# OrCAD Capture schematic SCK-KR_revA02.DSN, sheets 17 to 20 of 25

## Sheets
17 17_DisplayPort: size Custom
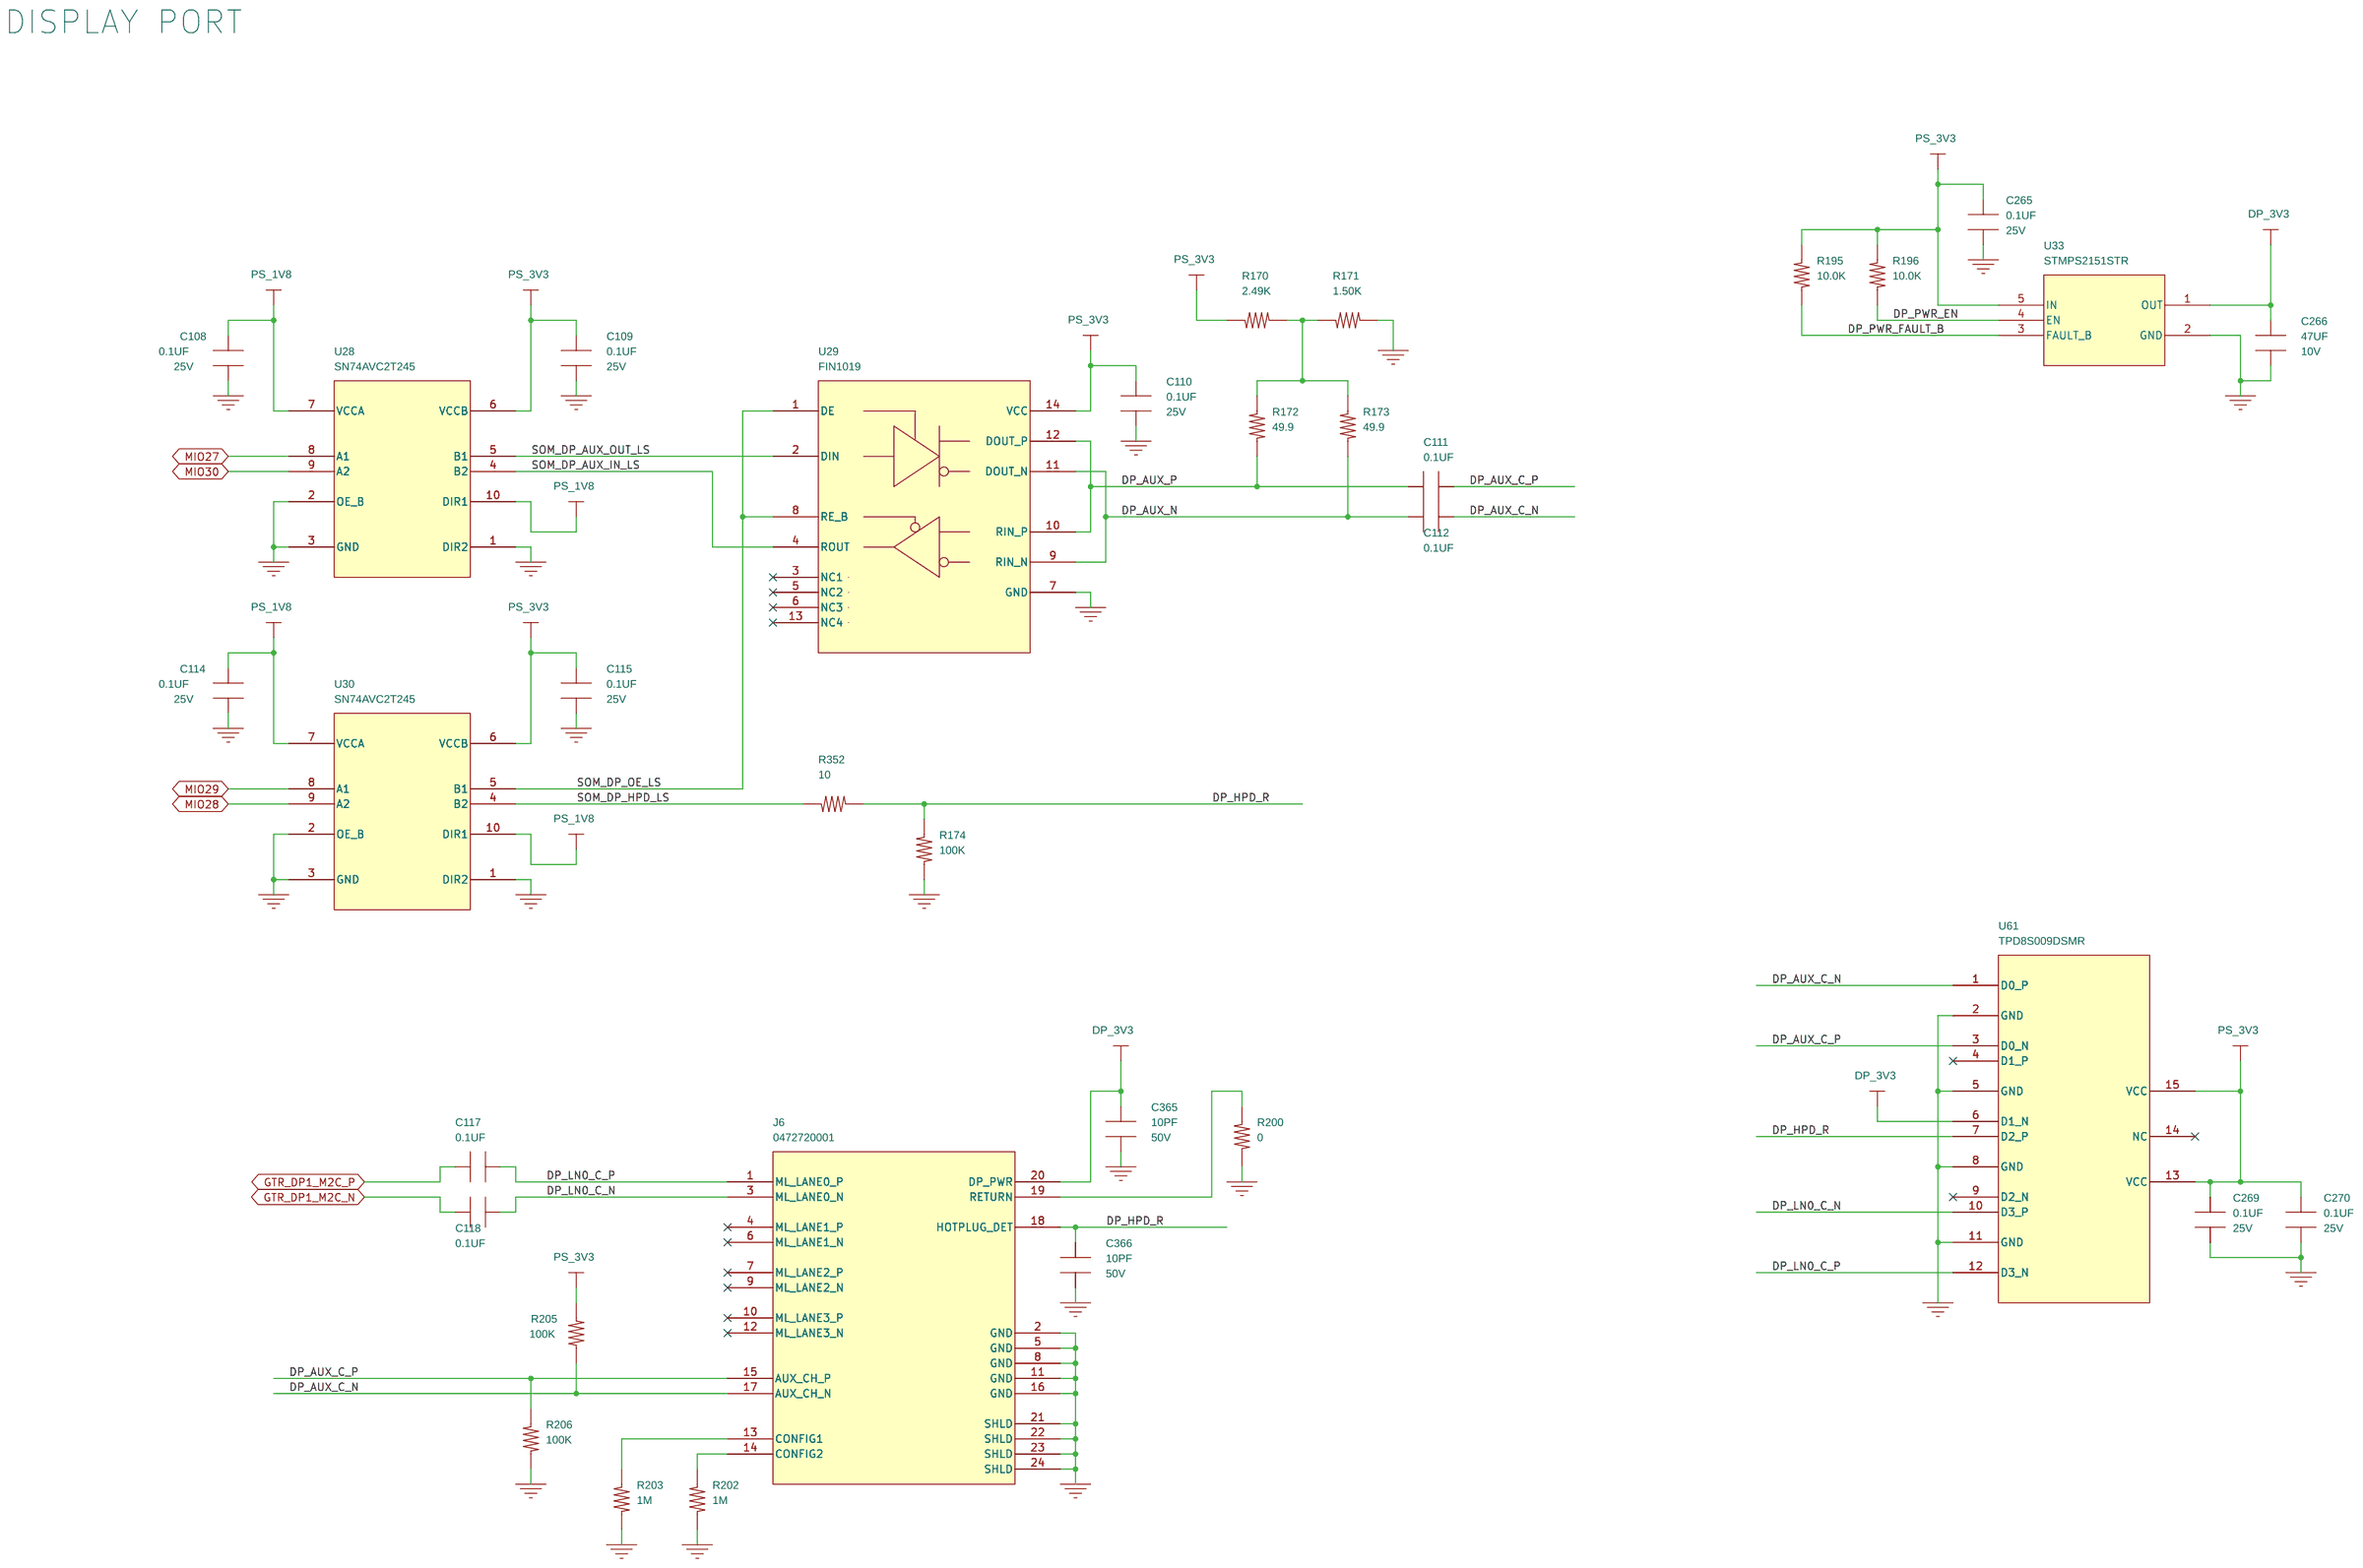
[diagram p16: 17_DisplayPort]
18 18_PS_GEM0: size Custom
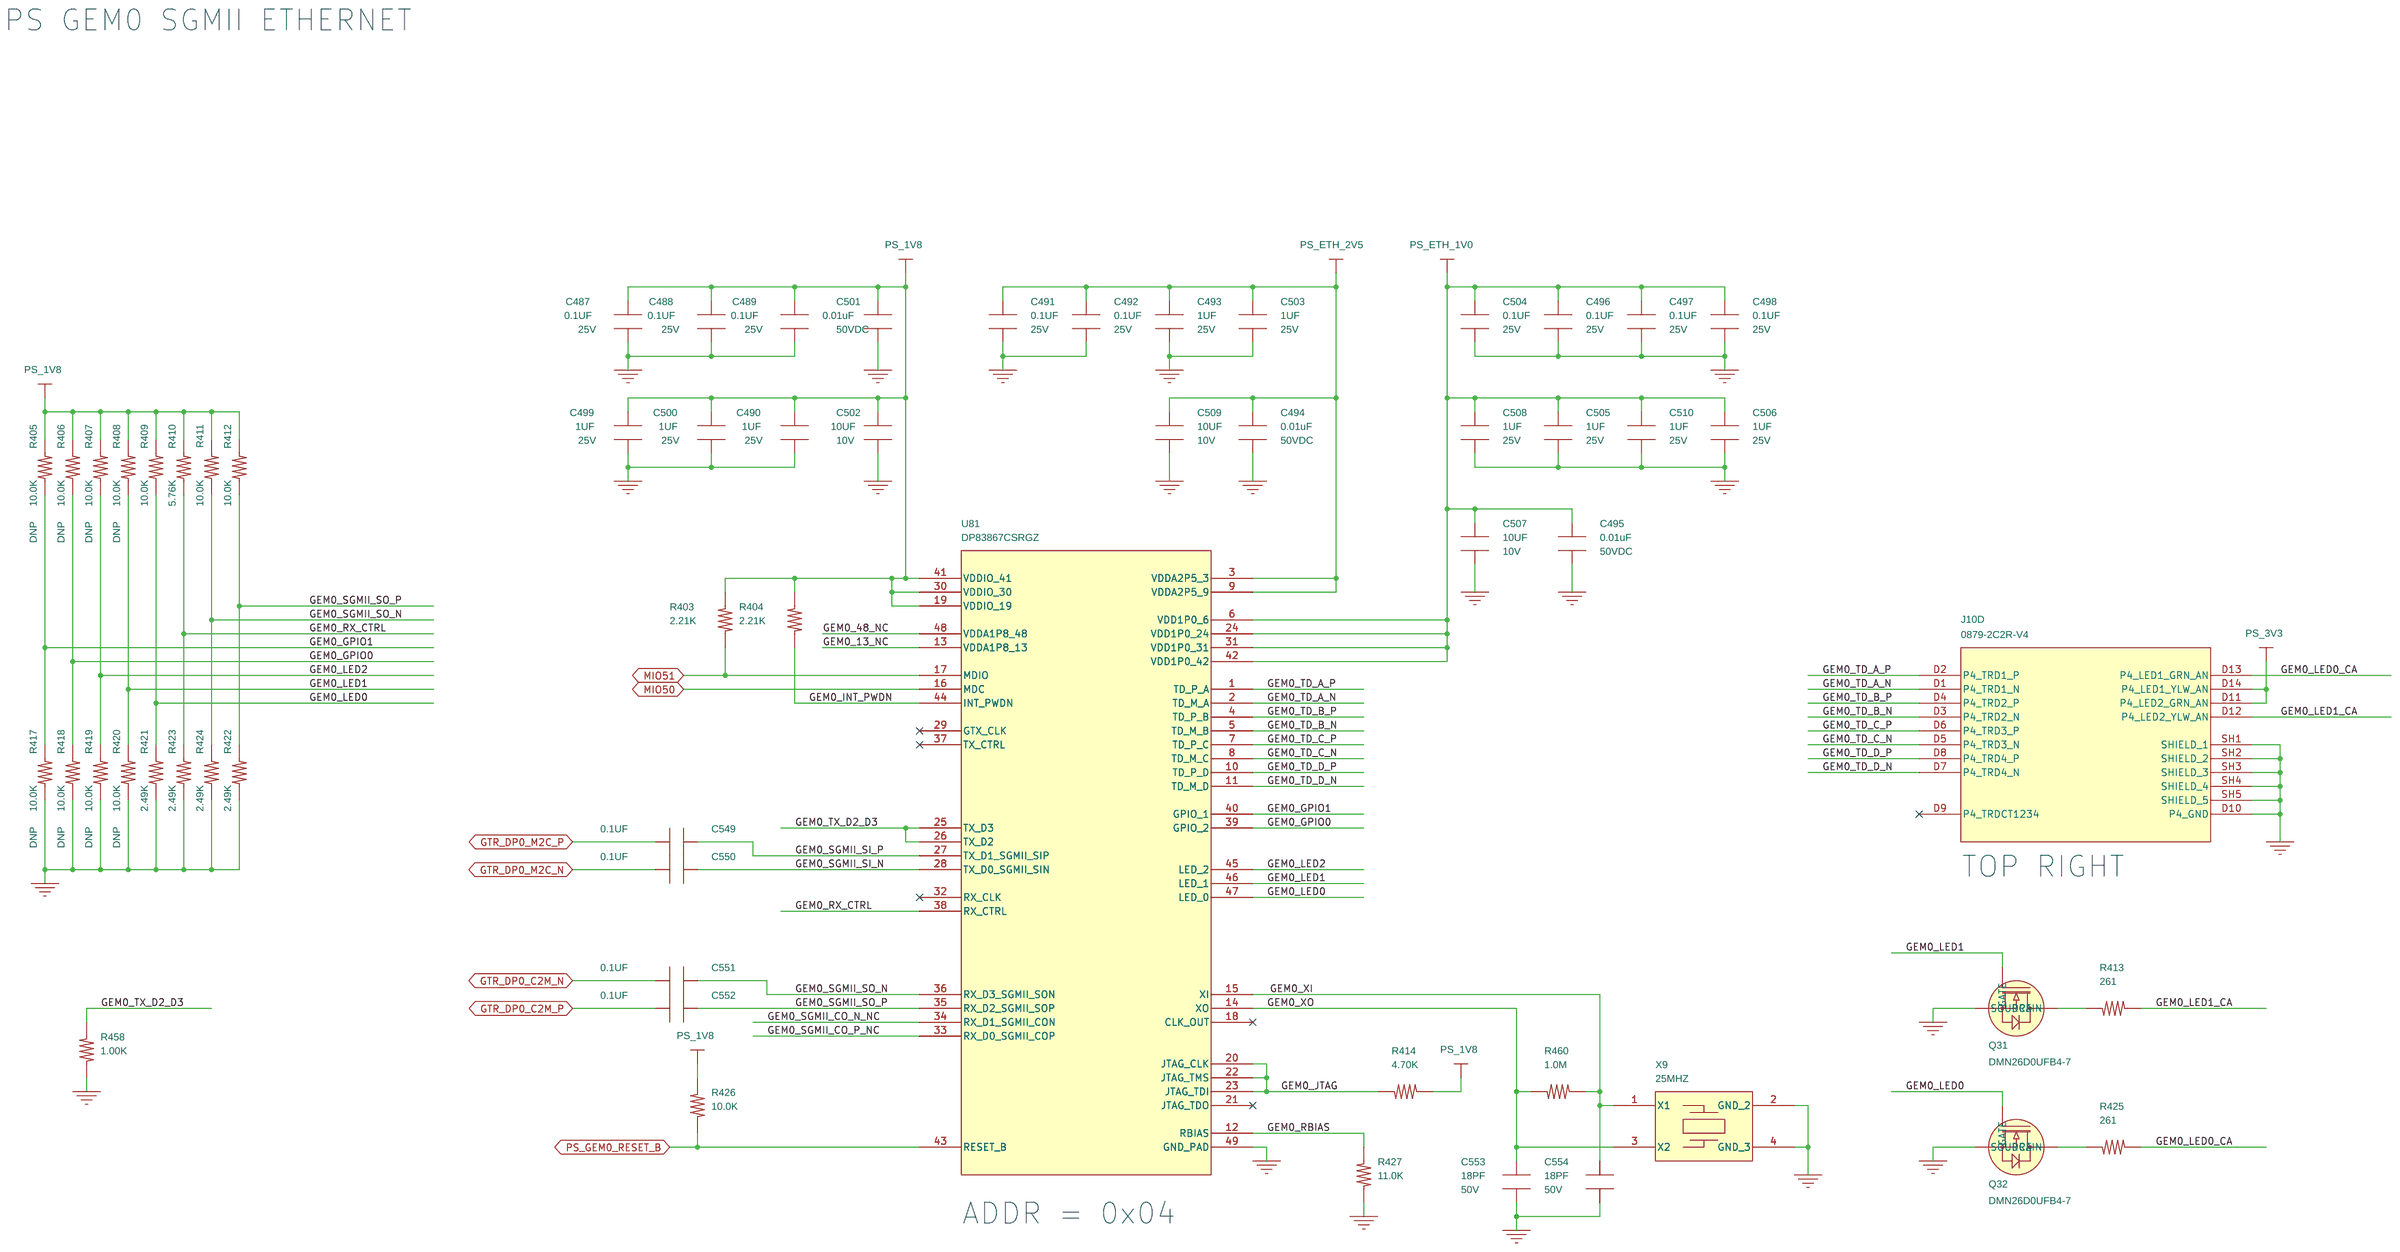
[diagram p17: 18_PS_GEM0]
19 19_PS_GEM1: size Custom
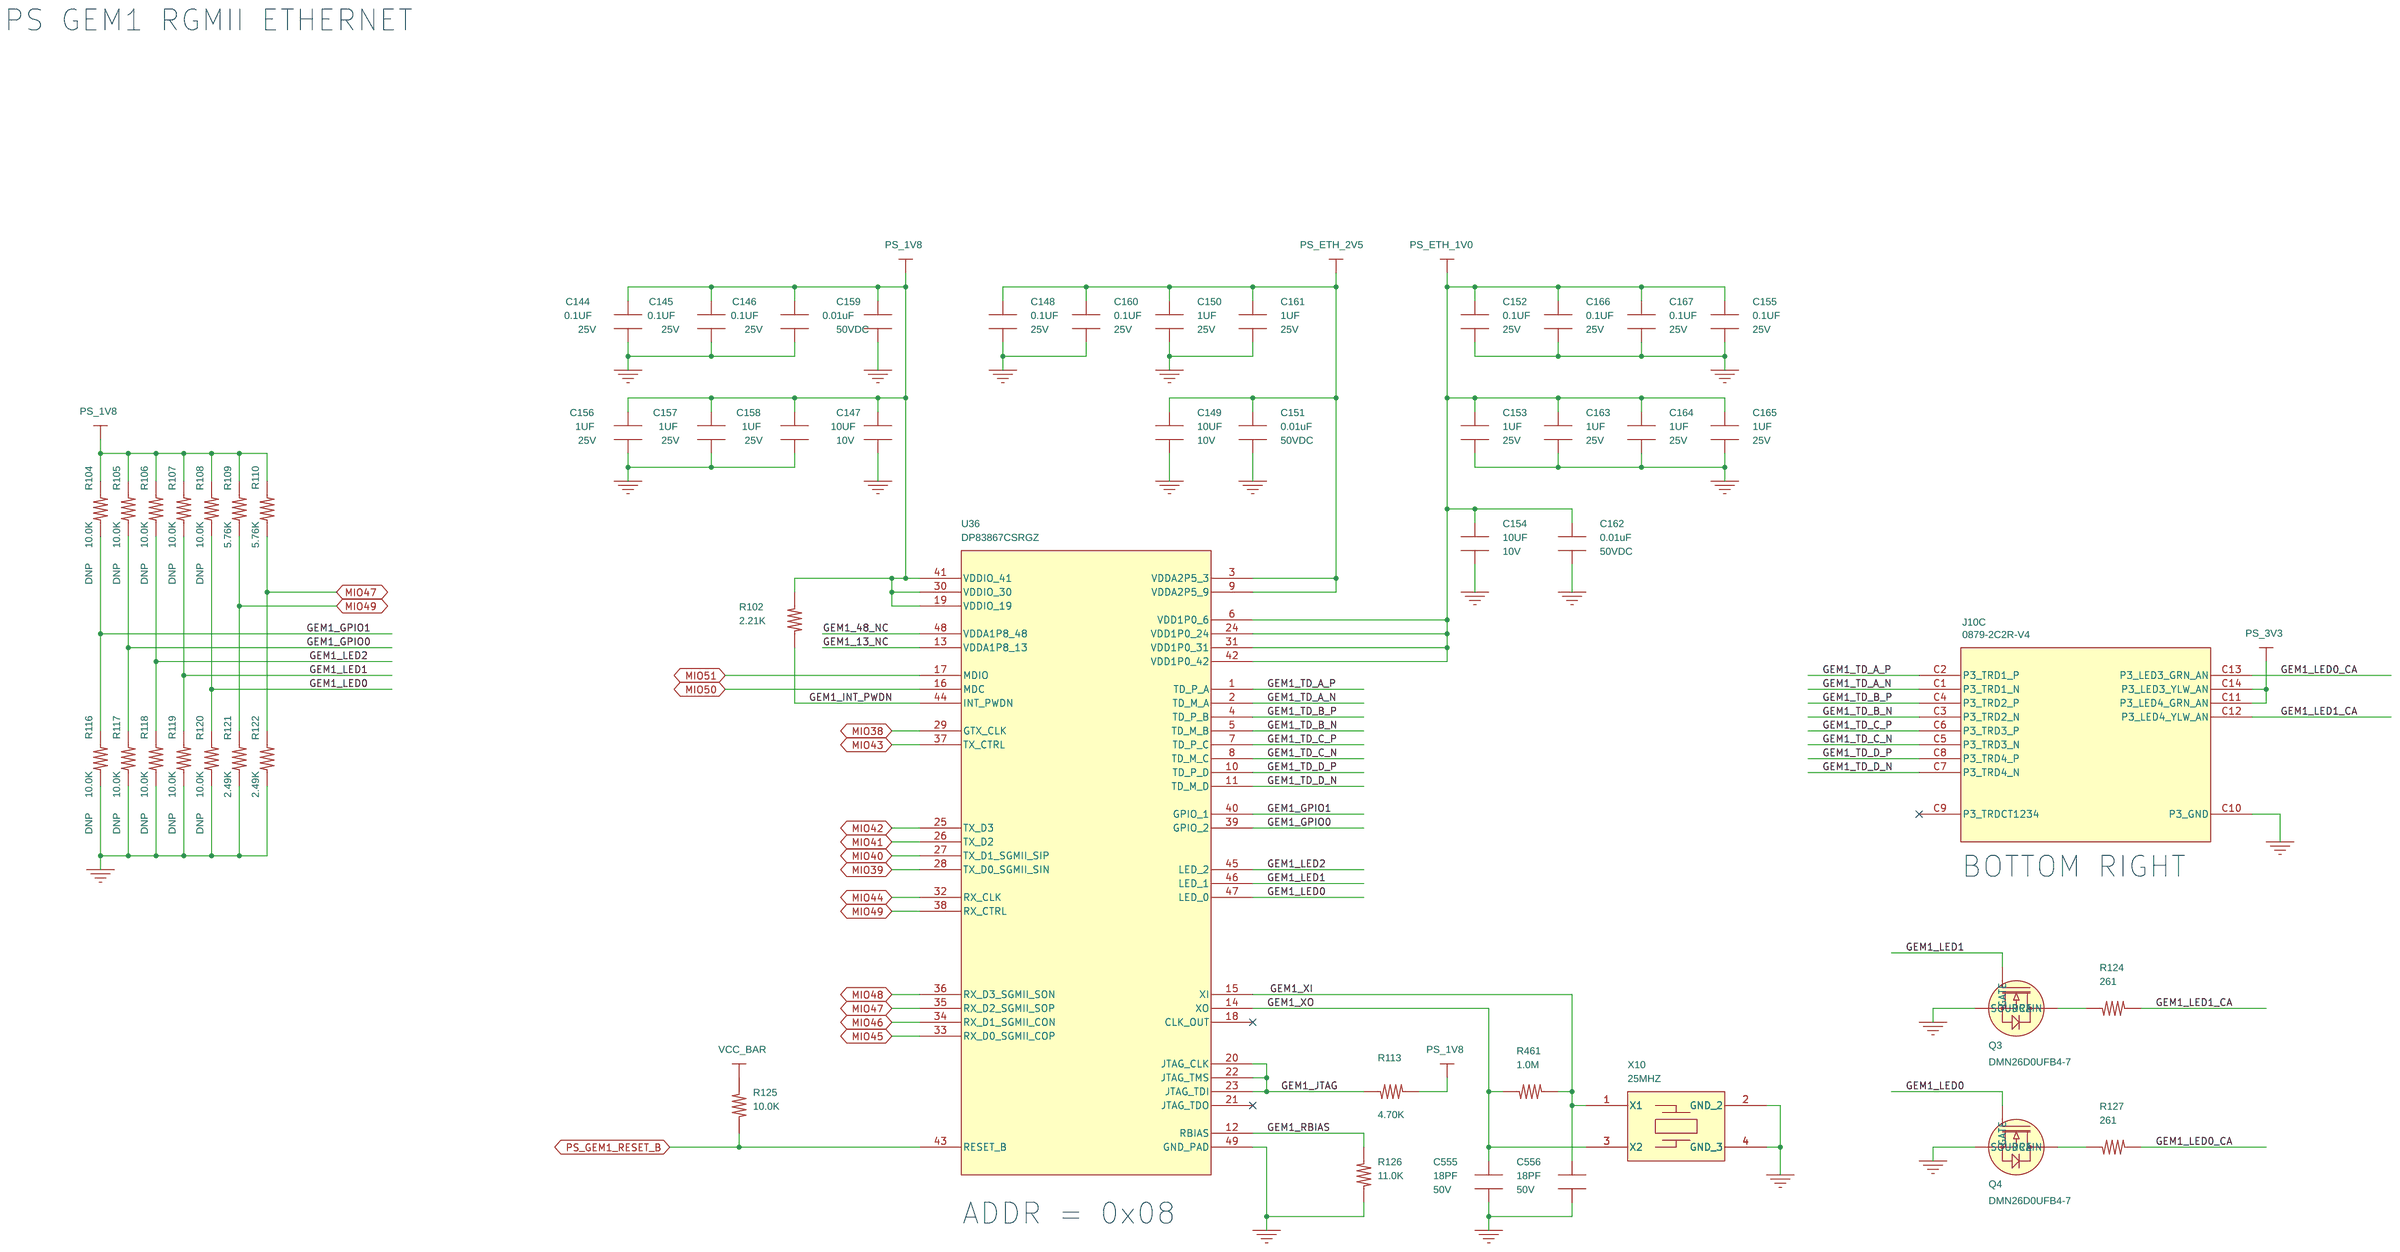
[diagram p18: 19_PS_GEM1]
20 20_PL_GEM2: size Custom
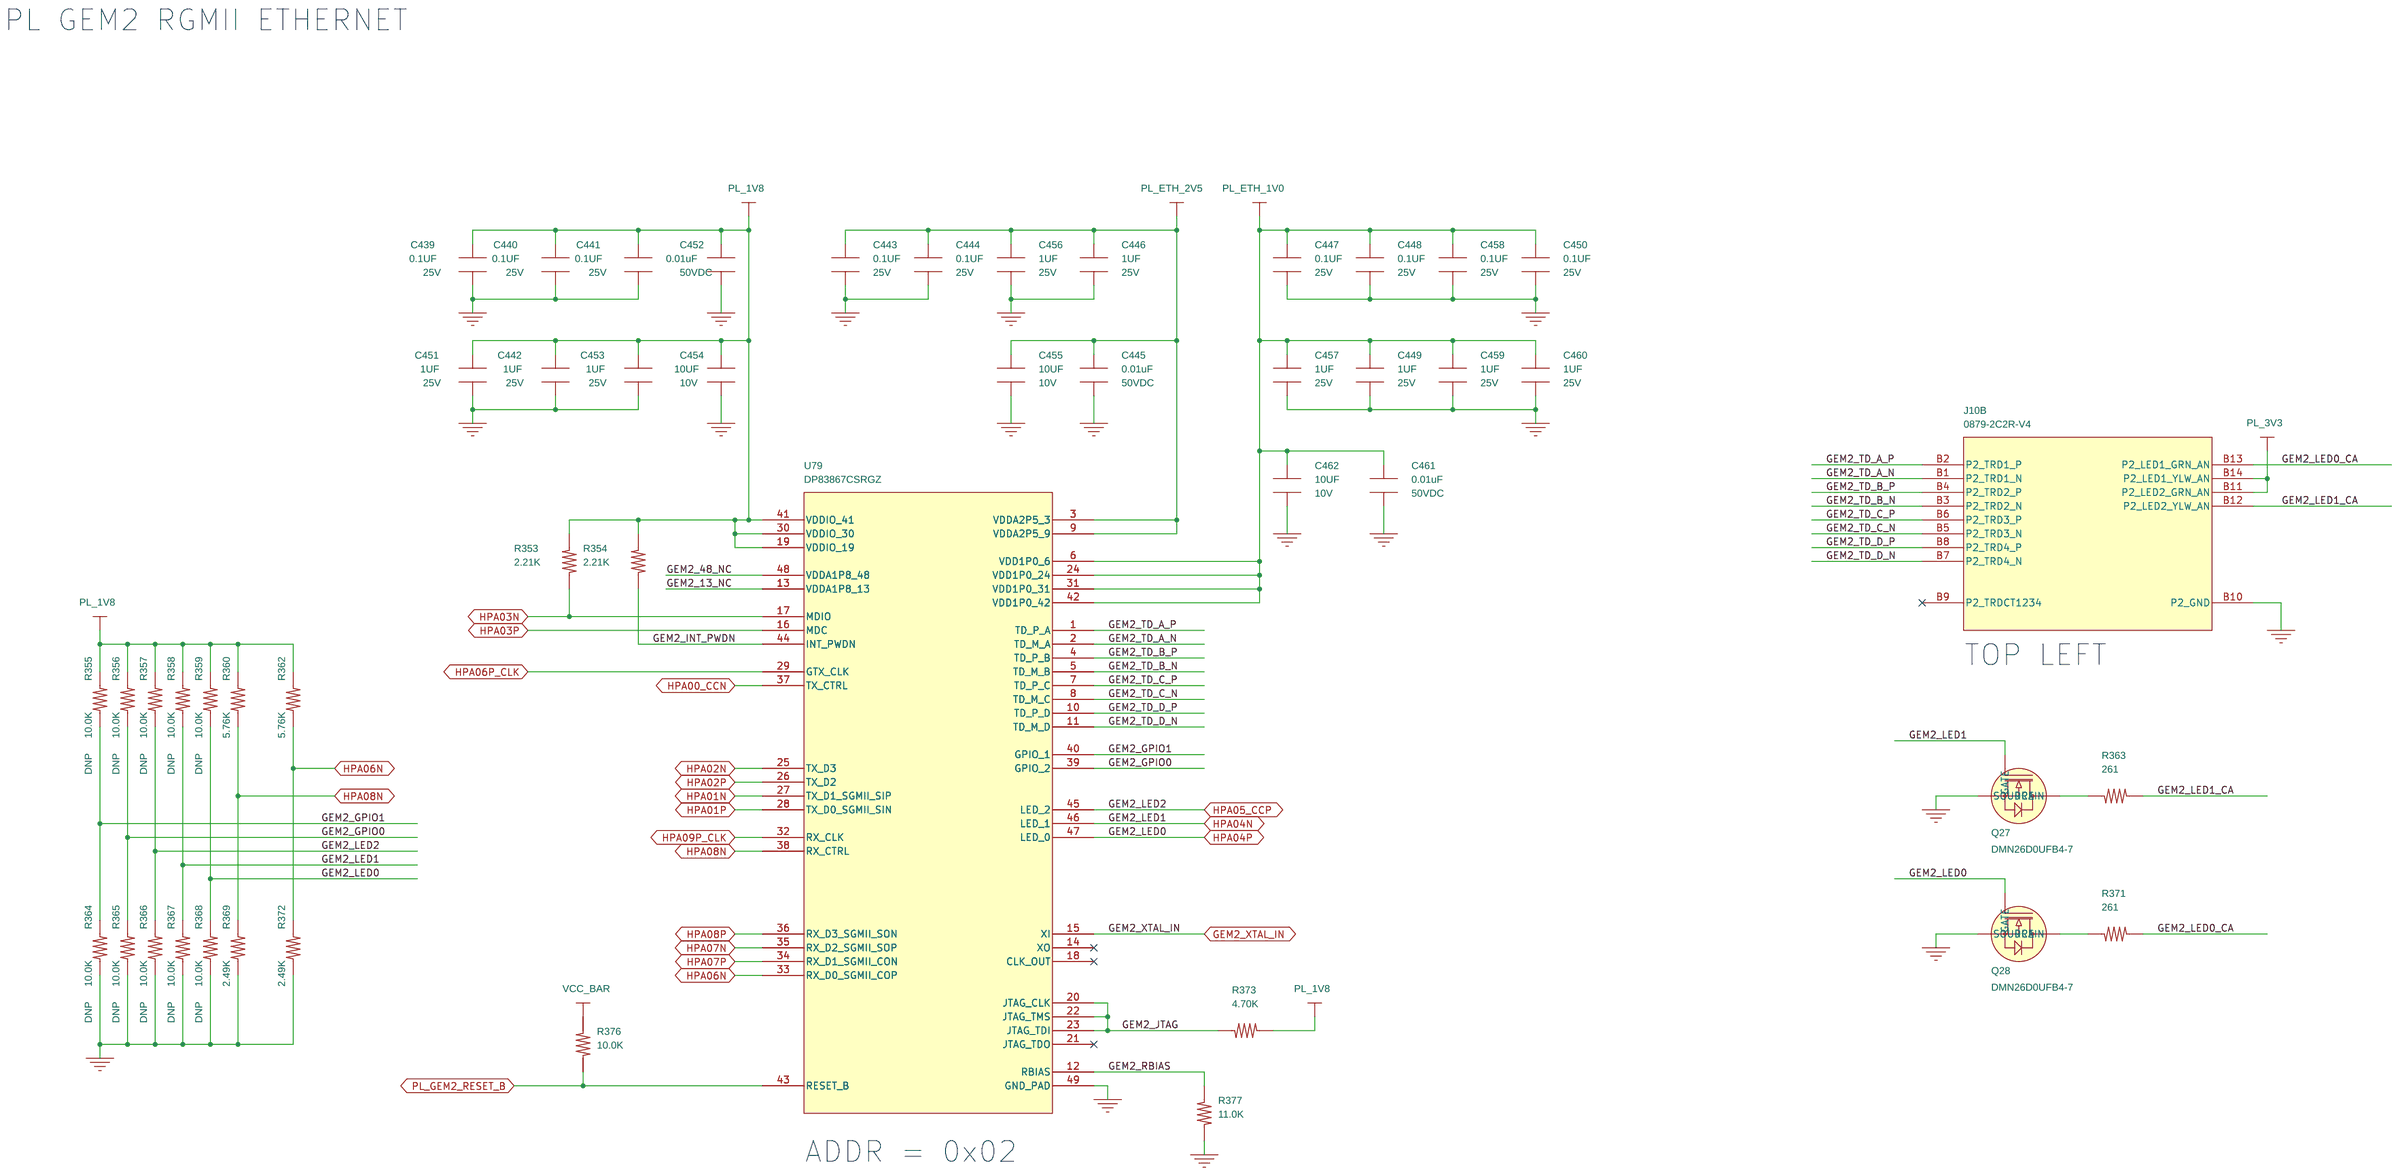
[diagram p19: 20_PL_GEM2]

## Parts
sheet 17_DisplayPort
C108  0.1UF  [CAPC100X50X55]
C109  0.1UF  [CAPC100X50X55]
C110  0.1UF  [CAPC100X50X55]
C111  0.1UF  [CAPC100X50X55]
C112  0.1UF  [CAPC100X50X55]
C114  0.1UF  [CAPC100X50X55]
C115  0.1UF  [CAPC100X50X55]
C117  0.1UF  [CAPC100X50X55]
C118  0.1UF  [CAPC100X50X55]
C265  0.1UF  [CAPC100X50X55]
C266  47UF  [CAPC200X125X125]
C269  0.1UF  [CAPC100X50X55]
C270  0.1UF  [CAPC100X50X55]
C365  10PF  [CAPC100X50X55]
C366  10PF  [CAPC100X50X55]
J6  0472720001  [CON_MOLEX_47272]
R170  2.49K  [RESC100X50X40]
R171  1.50K  [RESC100X50X40]
R172  49.9  [RESC100X50X40]
R173  49.9  [RESC100X50X40]
R174  100K  [RESC100X50X40]
R195  10.0K  [RESC100X50X40]
R196  10.0K  [RESC100X50X40]
R200  0  [RESC100X50X40]
R202  1M  [RESC100X50X40]
R203  1M  [RESC100X50X40]
R205  100K  [RESC100X50X40]
R206  100K  [RESC100X50X40]
R352  10  [RESC100X50X40]
U28  SN74AVC2T245  [QFN40P140X180X55-10]
U29  FIN1019  [TSSOP_14]
U30  SN74AVC2T245  [QFN40P140X180X55-10]
U33  STMPS2151STR  [SOT95P280X145_5]
U61  TPD8S009DSMR  [SON_15P]
sheet 18_PS_GEM0
C487  0.1UF  [CAPC100X50X55]
C488  0.1UF  [CAPC100X50X55]
C489  0.1UF  [CAPC100X50X55]
C490  1UF  [CAPC100X50X70]
C491  0.1UF  [CAPC100X50X55]
C492  0.1UF  [CAPC100X50X55]
C493  1UF  [CAPC100X50X70]
C494  0.01uF  [CAPC100X50X55]
C495  0.01uF  [CAPC100X50X55]
C496  0.1UF  [CAPC100X50X55]
C497  0.1UF  [CAPC100X50X55]
C498  0.1UF  [CAPC100X50X55]
C499  1UF  [CAPC100X50X70]
C500  1UF  [CAPC100X50X70]
C501  0.01uF  [CAPC100X50X55]
C502  10UF  [CAPC100X50X70]
C503  1UF  [CAPC100X50X70]
C504  0.1UF  [CAPC100X50X55]
C505  1UF  [CAPC100X50X70]
C506  1UF  [CAPC100X50X70]
C507  10UF  [CAPC100X50X70]
C508  1UF  [CAPC100X50X70]
C509  10UF  [CAPC100X50X70]
C510  1UF  [CAPC100X50X70]
C549  0.1UF  [CAPC100X50X55]
C550  0.1UF  [CAPC100X50X55]
C551  0.1UF  [CAPC100X50X55]
C552  0.1UF  [CAPC100X50X55]
C553  18PF  [CAPC100X50X50]
C554  18PF  [CAPC100X50X50]
J10  0879-2C2R-V4  [CON_BEL_0879_2C2R_V4]  (sections A,B,C,D)
Q31  DMN26D0UFB4-7  [DFN_105X65x40_3]
Q32  DMN26D0UFB4-7  [DFN_105X65x40_3]
R403  2.21K  [RESC100X50X40]
R404  2.21K  [RESC100X50X40]
R405  10.0K  [RESC100X50X40]
R406  10.0K  [RESC100X50X40]
R407  10.0K  [RESC100X50X40]
R408  10.0K  [RESC100X50X40]
R409  10.0K  [RESC100X50X40]
R410  5.76K  [RESC100X50X40]
R411  10.0K  [RESC100X50X40]
R412  10.0K  [RESC100X50X40]
R413  261  [RESC100X50X40]
R414  4.70K  [RESC100X50X40]
R417  10.0K  [RESC100X50X40]
R418  10.0K  [RESC100X50X40]
R419  10.0K  [RESC100X50X40]
R420  10.0K  [RESC100X50X40]
R421  2.49K  [RESC100X50X40]
R422  2.49K  [RESC100X50X40]
R423  2.49K  [RESC100X50X40]
R424  2.49K  [RESC100X50X40]
R425  261  [RESC100X50X40]
R426  10.0K  [RESC100X50X40]
R427  11.0K  [RESC100X50X40]
R458  1.00K  [RESC100X50X40]
R460  1.0M  [RESC100X50X40]
U81  DP83867CSRGZ  [VQFN05P700X700X100_48_408EP]
X9  25MHZ  [XTAL_EPSON_FA238]
sheet 19_PS_GEM1
C144  0.1UF  [CAPC100X50X55]
C145  0.1UF  [CAPC100X50X55]
C146  0.1UF  [CAPC100X50X55]
C147  10UF  [CAPC100X50X70]
C148  0.1UF  [CAPC100X50X55]
C149  10UF  [CAPC100X50X70]
C150  1UF  [CAPC100X50X70]
C151  0.01uF  [CAPC100X50X55]
C152  0.1UF  [CAPC100X50X55]
C153  1UF  [CAPC100X50X70]
C154  10UF  [CAPC100X50X70]
C155  0.1UF  [CAPC100X50X55]
C156  1UF  [CAPC100X50X70]
C157  1UF  [CAPC100X50X70]
C158  1UF  [CAPC100X50X70]
C159  0.01uF  [CAPC100X50X55]
C160  0.1UF  [CAPC100X50X55]
C161  1UF  [CAPC100X50X70]
C162  0.01uF  [CAPC100X50X55]
C163  1UF  [CAPC100X50X70]
C164  1UF  [CAPC100X50X70]
C165  1UF  [CAPC100X50X70]
C166  0.1UF  [CAPC100X50X55]
C167  0.1UF  [CAPC100X50X55]
C555  18PF  [CAPC100X50X50]
C556  18PF  [CAPC100X50X50]
Q3  DMN26D0UFB4-7  [DFN_105X65x40_3]
Q4  DMN26D0UFB4-7  [DFN_105X65x40_3]
R102  2.21K  [RESC100X50X40]
R104  10.0K  [RESC100X50X40]
R105  10.0K  [RESC100X50X40]
R106  10.0K  [RESC100X50X40]
R107  10.0K  [RESC100X50X40]
R108  10.0K  [RESC100X50X40]
R109  5.76K  [RESC100X50X40]
R110  5.76K  [RESC100X50X40]
R113  4.70K  [RESC100X50X40]
R116  10.0K  [RESC100X50X40]
R117  10.0K  [RESC100X50X40]
R118  10.0K  [RESC100X50X40]
R119  10.0K  [RESC100X50X40]
R120  10.0K  [RESC100X50X40]
R121  2.49K  [RESC100X50X40]
R122  2.49K  [RESC100X50X40]
R124  261  [RESC100X50X40]
R125  10.0K  [RESC100X50X40]
R126  11.0K  [RESC100X50X40]
R127  261  [RESC100X50X40]
R461  1.0M  [RESC100X50X40]
U36  DP83867CSRGZ  [VQFN05P700X700X100_48_408EP]
X10  25MHZ  [XTAL_EPSON_FA238]
sheet 20_PL_GEM2
C439  0.1UF  [CAPC100X50X55]
C440  0.1UF  [CAPC100X50X55]
C441  0.1UF  [CAPC100X50X55]
C442  1UF  [CAPC100X50X70]
C443  0.1UF  [CAPC100X50X55]
C444  0.1UF  [CAPC100X50X55]
C445  0.01uF  [CAPC100X50X55]
C446  1UF  [CAPC100X50X70]
C447  0.1UF  [CAPC100X50X55]
C448  0.1UF  [CAPC100X50X55]
C449  1UF  [CAPC100X50X70]
C450  0.1UF  [CAPC100X50X55]
C451  1UF  [CAPC100X50X70]
C452  0.01uF  [CAPC100X50X55]
C453  1UF  [CAPC100X50X70]
C454  10UF  [CAPC100X50X70]
C455  10UF  [CAPC100X50X70]
C456  1UF  [CAPC100X50X70]
C457  1UF  [CAPC100X50X70]
C458  0.1UF  [CAPC100X50X55]
C459  1UF  [CAPC100X50X70]
C460  1UF  [CAPC100X50X70]
C461  0.01uF  [CAPC100X50X55]
C462  10UF  [CAPC100X50X70]
Q27  DMN26D0UFB4-7  [DFN_105X65x40_3]
Q28  DMN26D0UFB4-7  [DFN_105X65x40_3]
R353  2.21K  [RESC100X50X40]
R354  2.21K  [RESC100X50X40]
R355  10.0K  [RESC100X50X40]
R356  10.0K  [RESC100X50X40]
R357  10.0K  [RESC100X50X40]
R358  10.0K  [RESC100X50X40]
R359  10.0K  [RESC100X50X40]
R360  5.76K  [RESC100X50X40]
R362  5.76K  [RESC100X50X40]
R363  261  [RESC100X50X40]
R364  10.0K  [RESC100X50X40]
R365  10.0K  [RESC100X50X40]
R366  10.0K  [RESC100X50X40]
R367  10.0K  [RESC100X50X40]
R368  10.0K  [RESC100X50X40]
R369  2.49K  [RESC100X50X40]
R371  261  [RESC100X50X40]
R372  2.49K  [RESC100X50X40]
R373  4.70K  [RESC100X50X40]
R376  10.0K  [RESC100X50X40]
R377  11.0K  [RESC100X50X40]
U79  DP83867CSRGZ  [VQFN05P700X700X100_48_408EP]

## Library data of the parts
C108-C112 C114 C115 C117 C118 C144-C146 C148 C152 C155 C160 C166 C167 C439-C441 C443 C444 C447 C448 C450 C458 C487-C489 C491 C492 C496-C498 C504 C549-C552 = CAP_NP: Cap Cer 100nF 10% 25V X5R 0402; ALT_SYMBOLS: CAPC100X50X55RND; Agile Part Number: CAP-00068-01; CIP Link: http://xsjbrdwin1/CIP-E/Component/Index/All?pn=100040; Dielectric Type: X5R; Manufacturer: TAIYO YUDEN; Manufacturer PN: TMK105BJ104KV-F; OWNER: 4001; PRICE: 0.01; Part Type: CERAMIC; PartType: CERAMIC; ROHS: Yes; Tolerance: 10%; Voltage: 25V; barcode: 100040
C265 C269 C270 = CAP_NP: Cap Cer 100nF 10% 25V X5R 0402; ALT_SYMBOLS: CAPC100X50X55RND; Agile Part Number: CAP-00068-01; CIP Link: http://xsjbrdwin1/CIP-E/Component/Index/All?pn=100040; DEVICE: 0_1UF_0402_X7R_50V; Dielectric: X7R; Dielectric Type: X5R; MANF: TAIYO YUDEN; MANF_P/N: UMK105B7104KV-FR; Manufacturer: TAIYO YUDEN; Manufacturer PN: TMK105BJ104KV-F; OWNER: 6176; PRICE: 0.02; Part Type: CERAMIC; PartType: CERAMIC; ROHS: Yes; Tolerance: 10%; Voltage: 25V; barcode: 100040
C266 = CAP_NP: CAP CER 47UF 10V X5R 0805; ALT_SYMBOLS: CAPC200X125X125RND; Agile Part Number: CAP-00254-01; Barcode: 100335; CIP Link: http://xsjbrdwin1/CIP-E/Component/Index/All?pn=100335; Dielectric Type: X5R; Manufacturer: MURATA; Manufacturer PN: GRM21BR61A476ME15L; Part Type: CERAMIC; Tolerance: 20%; Voltage: 10V
C365 C366 = CAP_NP: Cap Cer 10pF 5% 50V C0G 0402; ALT_SYMBOLS: (0402,C402-25,CAPC100X50X55L25NRND,CAPC100X50X55L30NRND,CAPC100X50X55L30N); Agile Part Number: CAP-00115-01; Barcode: 100127; CIP Link: http://xsjbrdwin1/CIP-E/Component/Index/All?pn=100127; Dielectric Type: C0G, NP0; Manufacturer: MURATA; Manufacturer PN: GCM1555C1H100JA16D; Part Type: CERAMIC; Tolerance: 5%; Voltage: 50V
J6 = 0472720001: Conn Rcpt DisplayPort Female RA 20 Pos 0.5mm P Black SMT; Agile Part Number: CON-00139-01; Barcode: 400070; CIP Link: http://xsjbrdwin1/CIP-E/Component/Index/All?pn=400070; Manufacturer: MOLEX; Part Type: RECEPTACLE
R170 = RES: Res 2K49 1% 1/16W 100PPM 50V 0402; Agile Part Number: RES-00085-01; Barcode: 200049; CIP Link: http://xsjbrdwin1/CIP-E/Component/Index/All?pn=200049; Manufacturer: PANASONIC; Manufacturer PN: ERJ2RKF2491X; Part Type: SMT - 1%; Rated Power: 1/16W; Tolerance: 1%
R171 = RES: RES SMD 1.5K OHM 1% 1/10W 0402; Agile Part Number: RES-00012-01; Barcode: 200161; CIP Link: http://xsjbrdwin1/CIP-E/Component/Index/All?pn=200161; Manufacturer: PANASONIC; Manufacturer PN: ERJ-2RKF1501X; Part Type: SMT - 1%; Rated Power: 1/10W; Tolerance: 1%
R172 R173 = RES: Res 49R9 1% 1/16W 100PPM 50V 0402; ALT_SYMBOLS: RESC100X50X40RND; Agile Part Number: RES-00104-01; Barcode: 200073; CIP Link: http://xsjbrdwin1/CIP-E/Component/Index/All?pn=200073; Manufacturer: PANASONIC; Manufacturer PN: ERJ2RKF49R9X; Part Type: SMT - 1%; Rated Power: 1/16W; Tolerance: 1%
R174 R205 R206 = RES: Res 100K 1% 1/16W 100PPM 50V 0402; ALT_SYMBOLS: RESC100X50X40RND; Agile Part Number: RES-00011-01; Barcode: 200026; CIP Link: http://xsjbrdwin1/CIP-E/Component/Index/All?pn=200026; Manufacturer: PANASONIC; Manufacturer PN: ERJ2RKF1003X; Part Type: SMT - 1%; Rated Power: 1/16W; Tolerance: 1%
R195 R196 = RES: Res 10K 1% 1/16W 100PPM 50V 0402; ALT_SYMBOLS: RESC100X50X40RND; Agile Part Number: RES-00030-01; Barcode: 200025; CIP Link: http://xsjbrdwin1/CIP-E/Component/Index/All?pn=200025; Manufacturer: PANASONIC; Manufacturer PN: ERJ2RKF1002X; Part Type: SMT - 1%; Rated Power: 1/16W; Tolerance: 1%
R200 = RES: Res 0R 50mR 1A 0402; ALT_SYMBOLS: RESC100X50X40RND; Agile Part Number: RES-00010-01; Barcode: 200012; CIP Link: http://xsjbrdwin1/CIP-E/Component/Index/All?pn=200012; Manufacturer: PANASONIC; Manufacturer PN: ERJ2GE0R00X; Part Type: SMT - 5%; Tolerance: 5%
R202 R203 = RES: RES SMD 1M OHM 1% 1/16W 0402; ALT_SYMBOLS: RESC100X50X40RND; Agile Part Number: RES-00332-01; Barcode: 200368; CIP Link: http://xsjbrdwin1/CIP-E/Component/Index/All?pn=200368; Manufacturer: VISHAY DALE; Manufacturer PN: CRCW04021M00FKED; Part Type: SMT - 1%; Rated Power: 1/16W; Tolerance: 1%
R352 = RES: Res 10R 1% 1/16W 100PPM 50V 0402; ALT_SYMBOLS: RESC100X50X40RND; Agile Part Number: RES-00025-01; Barcode: 200028; CIP Link: http://xsjbrdwin1/CIP-E/Component/Index/All?pn=200028; Part Type: SMT - 1%; Rated Power: 1/16W; Tolerance: 1%
U28 U30 = SN74AVC2T245: IC Lvl Trans 2-Bit Bidir 500Mbps 1.2-3.6V 50mA UQFN-10; Agile Part Number: ICS-00048-01; Barcode: 500012; CIP Link: http://xsjbrdwin1/CIP-E/Component/Index/All?pn=500012; Manufacturer: TEXAS INSTRUMENTS; Manufacturer PN: SN74AVC2T245RSWR; Part Type: BUS TRANSCEIVER
U29 = FIN1019: IC Lvl Trans LVTTL-LVDS Diff 400Mbps 3.3V 2.5nSec TSSOP-14; Agile Part Number: ICS-00279-01; Barcode: 500414; CIP Link: http://xsjbrdwin1/CIP-E/Component/Index/All?pn=500414; Manufacturer: FAIRCHILD; Manufacturer PN: FIN1019MTCX; Part Type: LVDS DRIVER/RECEIVER
U33 = STMPS2151: IC Switch Power 500mA 2.7-5.5V 110mR SOT23-5; Agile Part Number: ICS-00662-01; Barcode: 50000178; CIP Link: http://xsjbrdwin1/CIP-E/Component/Index/All?pn=50000178; Manufacturer: STMicroelectronics; Part Type: LOAD SWITCH; Supply Voltage: Not Required; Datasheet: http://www.st.com/content/ccc/resource/technical/document/datasheet/e8/d7/48/25/eb/87/45/b3/CD00167470.pdf/files/CD00167470.pdf/jcr:content/translations/en.CD00167470.pdf
U61 = TPD8S009DSMR: TVSD 8-Ch 5.5V 2.5A 25W 4GHz SON-15 8KV Contact Discharge; Agile Part Number: ICS-00196-01; Barcode: 500262; CIP Link: http://xsjbrdwin1/CIP-E/Component/Index/All?pn=500262; Manufacturer: TEXAS INSTRUMENTS; Part Type: ESD PROTECTOR
C150 C153 C156-C158 C161 C163-C165 C442 C446 C449 C451 C453 C456 C457 C459 C460 C490 C493 C499 C500 C503 C505 C506 C508 C510 = CAP_NP: Cap Cer 1uF 10% 25V X6S 0402; ALT_SYMBOLS: CAPC100X50X55RND; Agile Part Number: CAP-00009-01; Barcode: 100269; CIP Link: http://xsjbrdwin1/CIP-E/Component/Index/All?pn=100269; Dielectric Type: X6S; Manufacturer: MURATA; Manufacturer PN: GRM155C81E105KE11D; Part Type: CERAMIC; Tolerance: 10%; Voltage: 25V
C151 C159 C162 C445 C452 C461 C494 C495 C501 = CAP_NP: Cap Cer 10nF 10% 50V X7R 0402; ALT_SYMBOLS: CAPC100X50X55RND; Agile Part Number: CAP-00031-01; CIP Link: http://xsjbrdwin1/CIP-E/Component/Index/All?pn=100003; Dielectric Type: X7R; Manufacturer: Yageo; Manufacturer PN: CC0402KRX7R9BB103; OWNER: 4001; PRICE: 0; Part Type: CERAMIC; PartType: CERAMIC; ROHS: Yes; Tolerance: 10%; Voltage: 50VDC; barcode: 100003; Datasheet: http://download.siliconexpert.com/pdfs/2017/7/31/11/40/26/700/yageo_/manual/1073881636569039upy-gphc_x7r_6.3v-to-50v_18.pdf
C147 C149 C154 C454 C455 C462 C502 C507 C509 = CAP_NP: Cap Cer 10uF 20% 10V X5R 0402; Agile Part Number: CAP-00170-01; CIP Link: http://xsjbrdwin1/CIP-E/Component/Index/All?pn=100197; Dielectric Type: X5R; Manufacturer: SAMSUNG; Manufacturer PN: CL05A106MP5NUNC; OWNER: 3709; PRICE: 0.09; Part Type: CERAMIC; PartType: CERAMIC; ROHS: Yes; Tolerance: 20%; Voltage: 10V; barcode: 100197
C553-C556 = CAP_NP: Cap Cer 18pF 2% 50% C0G 0402; ALT_SYMBOLS: CAPC100X50X50RND; Agile Part Number: CAP-00084-01; Barcode: 100065; CIP Link: http://xsjbrdwin1/CIP-E/Component/Index/All?pn=100065; Dielectric Type: NPO; Part Type: CERAMIC; Tolerance: 5%; Voltage: 50V
J10 = RJ45_0879-2C2R-V4: Conn Rcpt RJ-45 1000Base-T RA  Quad 2x2 1.27mm P TH 4-LED Y/G Magnetics; Agile Part Number: CON-00474-01; Barcode: 40000147; CIP Link: http://xsjbrdwin1/CIP-E/Component/Index/All?pn=40000147; Part Type: Unassigned Part Type
Q3 Q4 Q27 Q28 Q31 Q32 = DMN26D0UFB4: MOSFET N-CH 20V 230MA DFN; Agile Part Number: TRN-00054-01; Barcode: 83000008; CIP Link: http://xsjbrdwin1/CIP-E/Component/Index/All?pn=83000008; Manufacturer: Diodes Incorporated; Part Type: FET; Rated Power: 350mW (Ta); Datasheet: https://www.diodes.com/assets/Datasheets/ds31775.pdf
R102 R353 R354 R403 R404 = RES: Res 2K21 1% 1/16W 100PPM 50V 0402; ALT_SYMBOLS: (0402,C402-25,RESC100X50X40L25NRND); Agile Part Number: RES-00023-01; Barcode: 200163; CIP Link: http://xsjbrdwin1/CIP-E/Component/Index/All?pn=200163; Manufacturer: PANASONIC; Manufacturer PN: ERJ2RKF2211X; OWNER: 3709; PRICE: 0; Part Type: SMT - 1%; PartType: SMT - 1%; Power: 1/10W; ROHS: Yes; Rated Power: 1/16W; Tolerance: 1%; primarykey: 254
R104-R108 R116-R120 R355-R359 R364-R368 R405-R408 R417-R420 = RES: Res 10K 1% 1/16W 100PPM 50V 0402; ALT_SYMBOLS: RESC100X50X40RND; ASSEMBLY_OPTIONS: DNP; Agile Part Number: RES-00030-01; Barcode: 200025; CIP Link: http://xsjbrdwin1/CIP-E/Component/Index/All?pn=200025; Manufacturer: PANASONIC; Manufacturer PN: ERJ2RKF1002X; OWNER: 3709; PRICE: 0; Part Type: SMT - 1%; PartType: SMT - DNP; Power: DNP; ROHS: Yes; Rated Power: 1/16W; Tolerance: 1%; primarykey: 73
R409 R411 R412 = RES: Res 10K 1% 1/16W 100PPM 50V 0402; ALT_SYMBOLS: RESC100X50X40RND; Agile Part Number: RES-00030-01; Barcode: 200025; CIP Link: http://xsjbrdwin1/CIP-E/Component/Index/All?pn=200025; Manufacturer: PANASONIC; Manufacturer PN: ERJ2RKF1002X; OWNER: 3709; PRICE: 0; Part Type: SMT - 1%; PartType: SMT - DNP; Power: DNP; ROHS: Yes; Rated Power: 1/16W; Tolerance: 1%; primarykey: 73
R109 R110 R360 R362 R410 = RES: RES 5.76 KOHM 1% 1/10W 0402; ALT_SYMBOLS: (0402,C402-25,RESC100X50X40L25NRND); Agile Part Number: RES-00179-01; Barcode: 200184; CIP Link: http://xsjbrdwin1/CIP-E/Component/Index/All?pn=200184; Manufacturer: PANASONIC; Manufacturer PN: ERJ-2RKF5761X; OWNER: 3709; PRICE: 0; Part Type: SMT - 1%; PartType: SMT - 1%; Power: 1/10W; ROHS: Yes; Rated Power: 1/10W; Tolerance: 1%; primarykey: 122
R124 R127 R363 R371 R413 R425 = RES: Res 261R 1% 1/16W 100PPM 50V 0402; ALT_SYMBOLS: RESC100X50X40RND; Agile Part Number: RES-00086-01; Barcode: 200050; CIP Link: http://xsjbrdwin1/CIP-E/Component/Index/All?pn=200050; Manufacturer: PANASONIC; Manufacturer PN: ERJ2RKF2610X; OWNER: 3501; PRICE: 0; Part Type: SMT - 1%; PartType: SMT - 1%; Power: 1/10W; ROHS: Yes; Rated Power: 1/16W; Tolerance: 1%; primarykey: 60
R113 R373 R414 = RES: Res 4K7 1% 1/16W 100PPM 50V 0402; ALT_SYMBOLS: RESC100X50X40RND; Agile Part Number: RES-00035-01; Barcode: 200067; CIP Link: http://xsjbrdwin1/CIP-E/Component/Index/All?pn=200067; Manufacturer: PANASONIC; Manufacturer PN: ERJ2RKF4701X; OWNER: 3670; PRICE: 0.01; Part Type: SMT - 1%; PartType: SMT - 1%; Power: 1/16W; ROHS: Yes; Rated Power: 1/16W; Tolerance: 1%; primarykey: 128
R121 R122 R369 R372 R421-R424 = RES: Res 2K49 1% 1/16W 100PPM 50V 0402; Agile Part Number: RES-00085-01; Barcode: 200049; CIP Link: http://xsjbrdwin1/CIP-E/Component/Index/All?pn=200049; Manufacturer: PANASONIC; Manufacturer PN: ERJ2RKF2491X; OWNER: 10460; PRICE: 0; Part Type: SMT - 1%; PartType: SMT - 1%; Power: 1/10W; ROHS: Yes; Rated Power: 1/16W; Tolerance: 1%; primarykey: 161
R125 R376 R426 = RES: Res 10K 1% 1/16W 100PPM 50V 0402; ALT_SYMBOLS: RESC100X50X40RND; Agile Part Number: RES-00030-01; Barcode: 200025; CIP Link: http://xsjbrdwin1/CIP-E/Component/Index/All?pn=200025; Manufacturer: PANASONIC; Manufacturer PN: ERJ2RKF1002X; OWNER: 4001; PRICE: 0; Part Type: SMT - 1%; PartType: SMT - 1%; Power: 1/10W; ROHS: Yes; Rated Power: 1/16W; Tolerance: 1%; primarykey: 1
R126 R377 R427 = RES: Res 11K 1% 1/16W 100PPM 50V 0402; ALT_SYMBOLS: RESC100X50X40RND; Agile Part Number: RES-00268-01; Barcode: 200289; CIP Link: http://xsjbrdwin1/CIP-E/Component/Index/All?pn=200289; Manufacturer: PANASONIC; Manufacturer PN: ERJ2RKF1102X; OWNER: 3501; PRICE: 0; Part Type: SMT - 1%; PartType: SMT - 1%; Power: 1/10W; ROHS: Yes; Rated Power: 1/16W; Tolerance: 1%; primarykey: 156
R458 = RES: Res 1K 1% 1/16W 100PPM 50V 0402; ALT_SYMBOLS: RESC100X50X40RND; Agile Part Number: RES-00027-01; Barcode: 200098; CIP Link: http://xsjbrdwin1/CIP-E/Component/Index/All?pn=200098; Manufacturer: PANASONIC; Manufacturer PN: ERJ2RKF1001X; OWNER: 4001; PRICE: 0; Part Type: SMT - 1%; PartType: SMT - 1%; Power: 1/16W; ROHS: Yes; Rated Power: 1/16W; Tolerance: 1%; primarykey: 7
R460 R461 = RES: Res 1M 5% 1/16W 200PPM 50V 0402; Agile Part Number: RES-00066-01; Barcode: 200013; CIP Link: http://xsjbrdwin1/CIP-E/Component/Index/All?pn=200013; Part Type: SMT - 5%; Rated Power: 1/16W; Tolerance: 5%
U36 U79 U81 = DP83867ISRGZ: IC PHY Ethernet Single 10/100/1000 Mbps 1.8-3.3V SGMII/RGMII VQFN-48; Agile Part Number: ICS-00865-01; Barcode: 50000316; CIP Link: http://xsjbrdwin1/CIP-E/Component/Index/All?pn=50000316; Part Type: ETHERNET PHY
X9 X10 = FA238: Xtal 25MHz 200uW 60R 18pF 62PPM 3225 SMT; Agile Part Number: XTL-00053-01; Barcode: 60000035; CIP Link: http://xsjbrdwin1/CIP-E/Component/Index/All?pn=60000035; Part Type: CRYSTAL

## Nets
GND: C108.2 C109.2 C110.2 C114.2 C115.2 C144.2 C145.2 C146.2 C147.2 C148.2 C149.2 C150.2 C151.2 C152.2 C153.2 C154.2 C155.2 C156.2 C157.2 C158.2 C159.2 C160.2 C161.2 C162.2 C163.2 C164.2 C165.2 C166.2 C167.2 C265.2 C266.2 C269.2 C270.2 C365.2 C366.2 C439.2 C440.2 C441.2 C442.2 C443.2 C444.2 C445.2 C446.2 C447.2 C448.2 C449.2 C450.2 C451.2 C452.2 C453.2 C454.2 C455.2 C456.2 C457.2 C458.2 C459.2 C460.2 C461.2 C462.2 C487.2 C488.2 C489.2 C490.2 C491.2 C492.2 C493.2 C494.2 C495.2 C496.2 C497.2 C498.2 C499.2 C500.2 C501.2 C502.2 C503.2 C504.2 C505.2 C506.2 C507.2 C508.2 C509.2 C510.2 C553.2 C554.2 C555.2 C556.2 J6.2(GND) J6.5(GND) J6.8(GND) J6.11(GND) J6.16(GND) J6.21(SHLD) J6.22(SHLD) J6.23(SHLD) J6.24(SHLD) J10.B10(P2_GND) J10.C10(P3_GND) J10.D10(P4_GND) J10.SH1(SHIELD_1) J10.SH2(SHIELD_2) J10.SH3(SHIELD_3) J10.SH4(SHIELD_4) J10.SH5(SHIELD_5) Q3.2(SOURCE) Q4.2(SOURCE) Q27.2(SOURCE) Q28.2(SOURCE) Q31.2(SOURCE) Q32.2(SOURCE) R116.2 R117.2 R118.2 R119.2 R120.2 R121.2 R122.2 R126.2 R171.2 R174.2 R200.2 R202.2 R203.2 R206.2 R364.2 R365.2 R366.2 R367.2 R368.2 R369.2 R372.2 R377.2 R417.2 R418.2 R419.2 R420.2 R421.2 R422.2 R423.2 R424.2 R427.2 R458.2 U28.1(DIR2) U28.2(OE_B) U28.3(GND) U29.7(GND) U30.1(DIR2) U30.2(OE_B) U30.3(GND) U33.2(GND) U36.49(GND_PAD) U61.2(GND) U61.5(GND) U61.8(GND) U61.11(GND) U79.49(GND_PAD) U81.49(GND_PAD) X9.2(GND) X9.4(GND_3) X10.2(GND) X10.4(GND_3) ; also on sheet 3 4 5 6 7 8 9 10 11 12 13 14 15 16 21 22 23 24 25
DP_3V3: C266.1 C365.1 J6.20(DP_PWR) U33.1(OUT) U61.6(D1_N)
DP_AUX_C_N: C112.2 J6.17(AUX_CH_N) R205.2 U61.1(D0_P)
DP_AUX_C_P: C111.2 J6.15(AUX_CH_P) R206.1 U61.3(D0_N)
DP_AUX_N: C112.1 R173.2 U29.9(RIN_N) U29.11(DOUT_N)
DP_AUX_P: C111.1 R172.2 U29.10(RIN_P) U29.12(DOUT_P)
DP_HPD_R: C366.1 J6.18(HOTPLUG_DET) R174.1 R352.2 U61.7(D2_P)
DP_LN0_C_N: C118.2 J6.3(ML_LANE0_N) U61.10(D3_P)
DP_LN0_C_P: C117.2 J6.1(ML_LANE0_P) U61.12(D3_N)
DP_PWR_EN: R196.2 U33.4(EN)
DP_PWR_FAULT_B: R195.2 U33.3(FAULT_B)
GEM0_13_NC: U81.13(VDDA1P8)
GEM0_48_NC: U81.48(VDDA1P8)
GEM0_GPIO0: R406.2 R418.1 U81.39(GPIO_2)
GEM0_GPIO1: R405.2 R417.1 U81.40(GPIO_1)
GEM0_INT_PWDN: R404.2 U81.44(INT_PWDN)
GEM0_JTAG: R414.2 U81.20(JTAG_CLK) U81.22(JTAG_TMS) U81.23(JTAG_TDI)
GEM0_LED0: Q32.1(GATE) R409.2 R421.1 U81.47(LED_0)
GEM0_LED0_CA: J10.D13(P4_LED1_GRN_AN) R425.2
GEM0_LED1: Q31.1(GATE) R408.2 R420.1 U81.46(LED_1)
GEM0_LED1_CA: J10.D12(P4_LED2_YLW_AN) R413.2
GEM0_LED2: R407.2 R419.1 U81.45(LED_2)
GEM0_RBIAS: R427.1 U81.12(RBIAS)
GEM0_RX_CTRL: R410.2 R423.1 U81.38(RX_CTRL)
GEM0_SGMII_CO_N_NC: U81.34(RX_D1_SGMII_CON)
GEM0_SGMII_CO_P_NC: U81.33(RX_D0_SGMII_COP)
GEM0_SGMII_SI_N: C550.2 U81.28(TX_D0_SGMII_SIN)
GEM0_SGMII_SI_P: C549.2 U81.27(TX_D1_SGMII_SIP)
GEM0_SGMII_SO_N: C551.2 R411.2 R424.1 U81.36(RX_D3_SGMII_SON)
GEM0_SGMII_SO_P: C552.2 R412.2 R422.1 U81.35(RX_D2_SGMII_SOP)
GEM0_TD_A_N: J10.D1(P4_TRD1_N) U81.2(TD_M_A)
GEM0_TD_A_P: J10.D2(P4_TRD1_P) U81.1(TD_P_A)
GEM0_TD_B_N: J10.D3(P4_TRD2_N) U81.5(TD_M_B)
GEM0_TD_B_P: J10.D4(P4_TRD2_P) U81.4(TD_P_B)
GEM0_TD_C_N: J10.D5(P4_TRD3_N) U81.8(TD_M_C)
GEM0_TD_C_P: J10.D6(P4_TRD3_P) U81.7(TD_P_C)
GEM0_TD_D_N: J10.D7(P4_TRD4_N) U81.11(TD_M_D)
GEM0_TD_D_P: J10.D8(P4_TRD4_P) U81.10(TD_P_D)
GEM0_TX_D2_D3: R458.1 U81.25(TX_D3) U81.26(TX_D2)
GEM0_XI: C554.1 R460.2 U81.15(XI) X9.1(X1)
GEM0_XO: C553.1 R460.1 U81.14(XO) X9.3(X2)
GEM1_13_NC: U36.13(VDDA1P8)
GEM1_48_NC: U36.48(VDDA1P8)
GEM1_GPIO0: R105.2 R117.1 U36.39(GPIO_2)
GEM1_GPIO1: R104.2 R116.1 U36.40(GPIO_1)
GEM1_INT_PWDN: R102.2 U36.44(INT_PWDN)
GEM1_JTAG: R113.2 U36.20(JTAG_CLK) U36.22(JTAG_TMS) U36.23(JTAG_TDI)
GEM1_LED0: Q4.1(GATE) R108.2 R120.1 U36.47(LED_0)
GEM1_LED0_CA: J10.C13(P3_LED3_GRN_AN) R127.2
GEM1_LED1: Q3.1(GATE) R107.2 R119.1 U36.46(LED_1)
GEM1_LED1_CA: J10.C12(P3_LED4_YLW_AN) R124.2
GEM1_LED2: R106.2 R118.1 U36.45(LED_2)
GEM1_RBIAS: R126.1 U36.12(RBIAS)
GEM1_TD_A_N: J10.C1(P3_TRD1_N) U36.2(TD_M_A)
GEM1_TD_A_P: J10.C2(P3_TRD1_P) U36.1(TD_P_A)
GEM1_TD_B_N: J10.C3(P3_TRD2_N) U36.5(TD_M_B)
GEM1_TD_B_P: J10.C4(P3_TRD2_P) U36.4(TD_P_B)
GEM1_TD_C_N: J10.C5(P3_TRD3_N) U36.8(TD_M_C)
GEM1_TD_C_P: J10.C6(P3_TRD3_P) U36.7(TD_P_C)
GEM1_TD_D_N: J10.C7(P3_TRD4_N) U36.11(TD_M_D)
GEM1_TD_D_P: J10.C8(P3_TRD4_P) U36.10(TD_P_D)
GEM1_XI: C556.1 R461.2 U36.15(XI) X10.1(X1)
GEM1_XO: C555.1 R461.1 U36.14(XO) X10.3(X2)
GEM2_13_NC: U79.13(VDDA1P8)
GEM2_48_NC: U79.48(VDDA1P8)
GEM2_GPIO0: R356.2 R365.1 U79.39(GPIO_2)
GEM2_GPIO1: R355.2 R364.1 U79.40(GPIO_1)
GEM2_INT_PWDN: R354.2 U79.44(INT_PWDN)
GEM2_JTAG: R373.2 U79.20(JTAG_CLK) U79.22(JTAG_TMS) U79.23(JTAG_TDI)
GEM2_LED0_CA: J10.B13(P2_LED1_GRN_AN) R371.2
GEM2_LED1_CA: J10.B12(P2_LED2_YLW_AN) R363.2
GEM2_RBIAS: R377.1 U79.12(RBIAS)
GEM2_TD_A_N: J10.B1(P2_TRD1_N) U79.2(TD_M_A)
GEM2_TD_A_P: J10.B2(P2_TRD1_P) U79.1(TD_P_A)
GEM2_TD_B_N: J10.B3(P2_TRD2_N) U79.5(TD_M_B)
GEM2_TD_B_P: J10.B4(P2_TRD2_P) U79.4(TD_P_B)
GEM2_TD_C_N: J10.B5(P2_TRD3_N) U79.8(TD_M_C)
GEM2_TD_C_P: J10.B6(P2_TRD3_P) U79.7(TD_P_C)
GEM2_TD_D_N: J10.B7(P2_TRD4_N) U79.11(TD_M_D)
GEM2_TD_D_P: J10.B8(P2_TRD4_P) U79.10(TD_P_D)
GEM2_XTAL_IN: U79.15(XI) ; also on sheet 16
GTR_DP0_C2M_N: C551.1 ; also on sheet 6
GTR_DP0_C2M_P: C552.1 ; also on sheet 6
GTR_DP0_M2C_N: C550.1 ; also on sheet 6
GTR_DP0_M2C_P: C549.1 ; also on sheet 6
GTR_DP1_M2C_N: C118.1 ; also on sheet 6
GTR_DP1_M2C_P: C117.1 ; also on sheet 6
HPA00_CCN: U79.37(TX_CTRL) ; also on sheet 6
HPA01N: U79.27(TX_D1_SGMII_SIP) ; also on sheet 6
HPA01P: U79.28(TX_D0_SGMII_SIN) ; also on sheet 6
HPA02N: U79.25(TX_D3) ; also on sheet 6
HPA02P: U79.26(TX_D2) ; also on sheet 6
HPA03N: R353.2 U79.17(MDIO) ; also on sheet 6
HPA03P: U79.16(MDC) ; also on sheet 6
HPA04N: Q27.1(GATE) R358.2 R367.1 U79.46(LED_1) ; also on sheet 6
HPA04P: Q28.1(GATE) R359.2 R368.1 U79.47(LED_0) ; also on sheet 6
HPA05_CCP: R357.2 R366.1 U79.45(LED_2) ; also on sheet 6
HPA06N: R362.2 R372.1 U79.33(RX_D0_SGMII_COP) ; also on sheet 6
HPA06P_CLK: U79.29(GTX_CLK) ; also on sheet 6
HPA07N: U79.35(RX_D2_SGMII_SOP) ; also on sheet 6
HPA07P: U79.34(RX_D1_SGMII_CON) ; also on sheet 6
HPA08N: R360.2 R369.1 U79.38(RX_CTRL) ; also on sheet 6
HPA08P: U79.36(RX_D3_SGMII_SON) ; also on sheet 6
HPA09P_CLK: U79.32(RX_CLK) ; also on sheet 6
MIO27: U28.8(A1) ; also on sheet 6
MIO28: U30.9(A2) ; also on sheet 6
MIO29: U30.8(A1) ; also on sheet 6
MIO30: U28.9(A2) ; also on sheet 6
MIO38: U36.29(GTX_CLK) ; also on sheet 6
MIO39: U36.28(TX_D0_SGMII_SIN) ; also on sheet 6
MIO40: U36.27(TX_D1_SGMII_SIP) ; also on sheet 6
MIO41: U36.26(TX_D2) ; also on sheet 6
MIO42: U36.25(TX_D3) ; also on sheet 6
MIO43: U36.37(TX_CTRL) ; also on sheet 6
MIO44: U36.32(RX_CLK) ; also on sheet 6
MIO45: U36.33(RX_D0_SGMII_COP) ; also on sheet 6
MIO46: U36.34(RX_D1_SGMII_CON) ; also on sheet 6
MIO47: R110.2 R122.1 U36.35(RX_D2_SGMII_SOP) ; also on sheet 6
MIO48: U36.36(RX_D3_SGMII_SON) ; also on sheet 6
MIO49: R109.2 R121.1 U36.38(RX_CTRL) ; also on sheet 6
MIO50: U36.16(MDC) U81.16(MDC) ; also on sheet 6
MIO51: R403.2 U36.17(MDIO) U81.17(MDIO) ; also on sheet 6
PL_1V8: C439.1 C440.1 C441.1 C442.1 C451.1 C452.1 C453.1 C454.1 R353.1 R354.1 R355.1 R356.1 R357.1 R358.1 R359.1 R360.1 R362.1 R373.1 R376.1 U79.19(VDDIO) U79.30(VDDIO) U79.41(VDDIO) ; also on sheet 5 6 7 13 16 21
PL_3V3: J10.B11(P2_LED2_GRN_AN) J10.B14(P2_LED1_YLW_AN) ; also on sheet 5 6 7 10 12 14 15 16 21
PL_ETH_1V0: C447.1 C448.1 C449.1 C450.1 C457.1 C458.1 C459.1 C460.1 C461.1 C462.1 U79.6(VDD1P0) U79.24(VDD1P0) U79.31(VDD1P0) U79.42(VDD1P0) ; also on sheet 5 21
PL_ETH_2V5: C443.1 C444.1 C445.1 C446.1 C455.1 C456.1 U79.3(VDDA2P5) U79.9(VDDA2P5) ; also on sheet 5 21
PL_GEM2_RESET_B: R376.2 U79.43(RESET_B) ; also on sheet 16
PS_1V8: C108.1 C114.1 C144.1 C145.1 C146.1 C147.1 C156.1 C157.1 C158.1 C159.1 C487.1 C488.1 C489.1 C490.1 C499.1 C500.1 C501.1 C502.1 R102.1 R104.1 R105.1 R106.1 R107.1 R108.1 R109.1 R110.1 R113.1 R125.1 R403.1 R404.1 R405.1 R406.1 R407.1 R408.1 R409.1 R410.1 R411.1 R412.1 R414.1 R426.1 U28.7(VCCA) U28.10(DIR1) U30.7(VCCA) U30.10(DIR1) U36.19(VDDIO) U36.30(VDDIO) U36.41(VDDIO) U81.19(VDDIO) U81.30(VDDIO) U81.41(VDDIO) ; also on sheet 4 8 9 15 16 24 25
PS_3V3: C109.1 C110.1 C115.1 C265.1 C269.1 C270.1 J10.C11(P3_LED4_GRN_AN) J10.C14(P3_LED3_YLW_AN) J10.D11(P4_LED2_GRN_AN) J10.D14(P4_LED1_YLW_AN) R170.1 R195.1 R196.1 R205.1 U28.6(VCCB) U29.14(VCC) U30.6(VCCB) U33.5(IN) U61.13(VCC) U61.15(VCC) ; also on sheet 4 15 16 22 24 25
PS_ETH_1V0: C152.1 C153.1 C154.1 C155.1 C162.1 C163.1 C164.1 C165.1 C166.1 C167.1 C495.1 C496.1 C497.1 C498.1 C504.1 C505.1 C506.1 C507.1 C508.1 C510.1 U36.6(VDD1P0) U36.24(VDD1P0) U36.31(VDD1P0) U36.42(VDD1P0) U81.6(VDD1P0) U81.24(VDD1P0) U81.31(VDD1P0) U81.42(VDD1P0) ; also on sheet 4
PS_ETH_2V5: C148.1 C149.1 C150.1 C151.1 C160.1 C161.1 C491.1 C492.1 C493.1 C494.1 C503.1 C509.1 U36.3(VDDA2P5) U36.9(VDDA2P5) U81.3(VDDA2P5) U81.9(VDDA2P5) ; also on sheet 4
PS_GEM0_RESET_B: R426.2 U81.43(RESET_B) ; also on sheet 16
PS_GEM1_RESET_B: R125.2 U36.43(RESET_B) ; also on sheet 16
SOM_DP_AUX_IN_LS: U28.4(B2) U29.4(ROUT)
SOM_DP_AUX_OUT_LS: U28.5(B1) U29.2(DIN)
SOM_DP_HPD_LS: R352.1 U30.4(B2)
SOM_DP_OE_LS: U29.1(DE) U29.8(RE_B) U30.5(B1)
N1592727: R170.2 R171.1 R172.1 R173.1
N3433845: J6.19(RETURN) R200.1
N3434397: J6.13(CONFIG1) R203.1
N3434417: J6.14(CONFIG2) R202.1
N3917930: Q27.3(DRAIN) R363.1
N3917978: Q28.3(DRAIN) R371.1
N3924610: Q31.3(DRAIN) R413.1
N3924658: Q32.3(DRAIN) R425.1
N3928736: Q3.3(DRAIN) R124.1
N3928738: Q4.3(DRAIN) R127.1

Not connected (* = marked no-connect by the designer): J6 4(ML_LANE1_P)* 6(ML_LANE1_N)* 7(ML_LANE2_P)* 9(ML_LANE2_N)* 10(ML_LANE3_P)* 12(ML_LANE3_N)*; J10 B9(P2_TRDCT1234)* C9(P3_TRDCT1234)* D9(P4_TRDCT1234)*; U29 3(NC1)* 5(NC2)* 6(NC3)* 13(NC4)*; U36 18(CLK_OUT)* 21(JTAG_TDO)*; U61 4(D1_P)* 9(D2_N)* 14(NC)*; U79 14(XO)* 18(CLK_OUT)* 21(JTAG_TDO)*; U81 18(CLK_OUT)* 21(JTAG_TDO)* 29(GTX_CLK)* 32(RX_CLK)* 37(TX_CTRL)*

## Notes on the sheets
sheet 17
- DISPLAY PORT
sheet 18
- PS GEM0 SGMII ETHERNET
- TOP RIGHT
- ADDR = 0x04
sheet 19
- PS GEM1 RGMII ETHERNET
- BOTTOM RIGHT
- ADDR = 0x08
sheet 20
- PL GEM2 RGMII ETHERNET
- TOP LEFT
- ADDR = 0x02
